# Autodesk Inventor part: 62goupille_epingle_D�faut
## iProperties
Created: 2011-01
Part Number: 62goupille_epingle_D�faut
Document SubType Name: Modeling
Designer: eric
Density: 1 g/cm^3
Mass: 1.09547 g
Surface Area: 14.7477 cm^2
Volume: 1.09547 cm^3
Author: eric
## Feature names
1. Base1
